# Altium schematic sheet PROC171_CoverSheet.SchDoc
size 431 x 279 mm; Date: Not shown in title block; ApprovedBy: Not shown in title block; CheckedBy: Not shown in title block; Author: Not shown in title block; CompanyName: Not shown in title block; Engineer: Shrinivas/Rakesh; Organization: Not shown in title block; Address1: Not shown in title block; Address2: Not shown in title block; Address3: Not shown in title block; Address4: Not shown in title block; DocumentNumber: 1; Rev: E1; SheetNumber: 1; SheetTotal: 26; PageSetup: Record=PageOptions¦CenterHorizontal=True¦CenterVertical=True¦PrintScale=1.00¦XCorrection=1.00¦YCorrection=1.00¦PrintKind=0¦BorderSize=5000000¦LeftOffset=0¦BottomOffset=0¦Orientation=2¦PaperLength=1000¦PaperWidth=1000¦Scale=100¦PaperSource=15¦PrintQuality=600¦MediaType=1¦DitherType=10¦PaperKind=Letter¦PrintScaleMode=1; Revision: E1
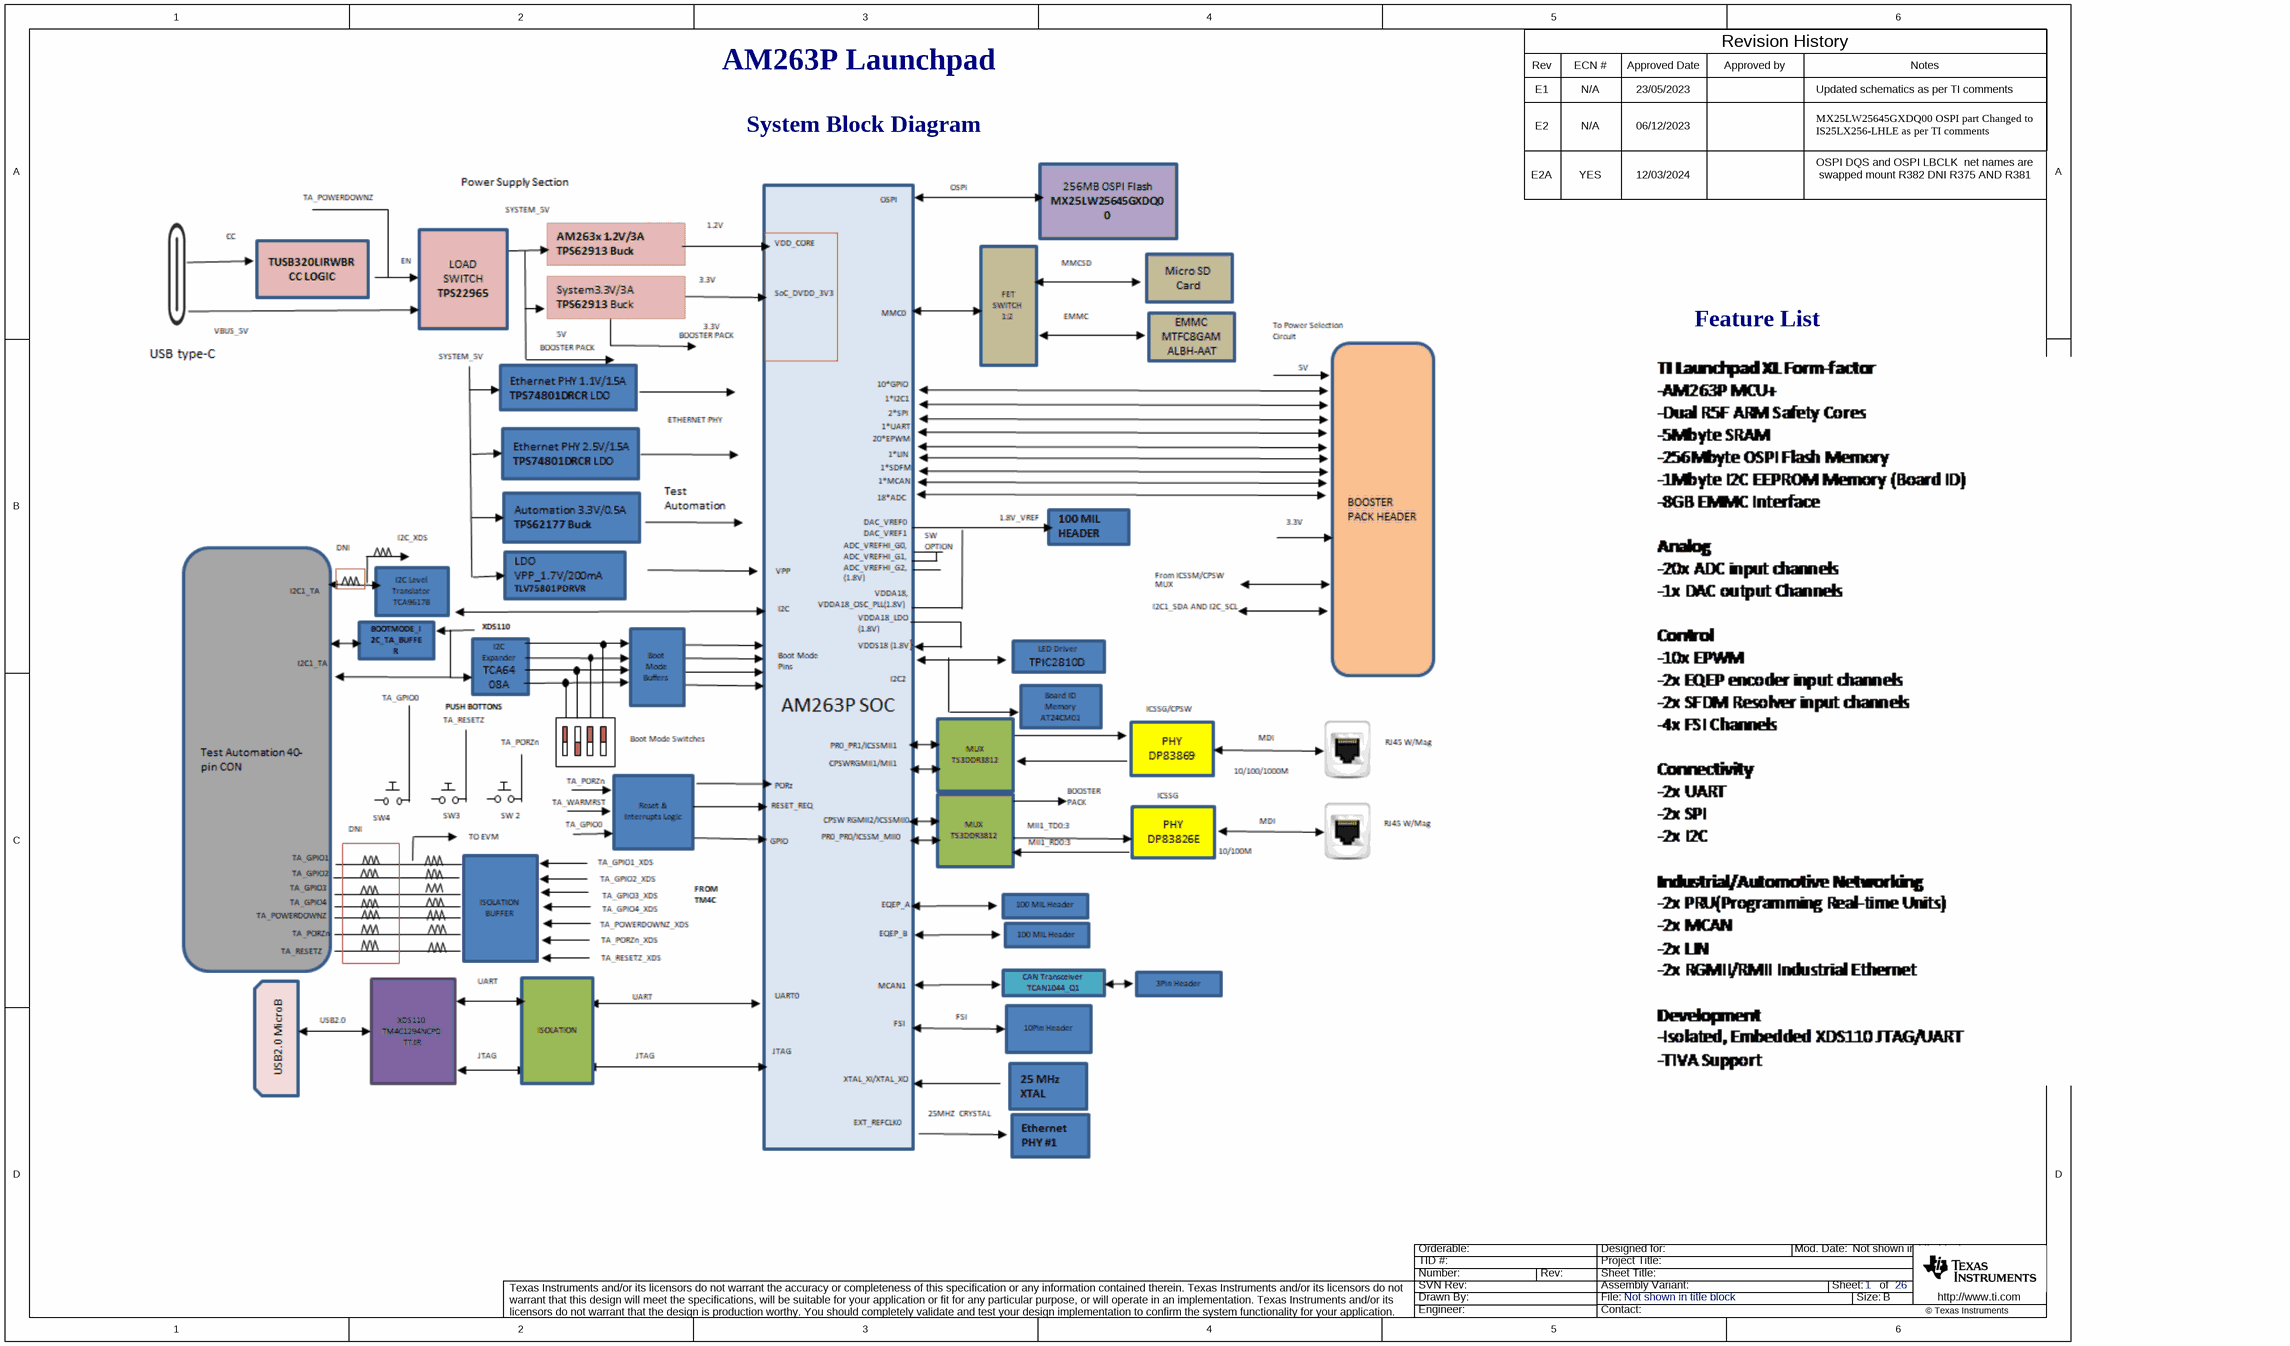
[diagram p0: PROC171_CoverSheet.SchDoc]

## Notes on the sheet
- AM263P Launchpad
- Rev
- E1
- ECN #
- N/A
- Approved Date
- 23/05/2023
- Approved by
- Revision History
- Updated schematics as per TI comments
- Notes
- System Block Diagram
- E2
- 06/12/2023
- MX25LW25645GXDQ00 OSPI part Changed to
- IS25LX256-LHLE as per TI comments
- E2A
- YES
- 12/03/2024
- OSPI DQS and OSPI LBCLK  net names are
- swapped mount R382 DNI R375 AND R381
- Feature List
